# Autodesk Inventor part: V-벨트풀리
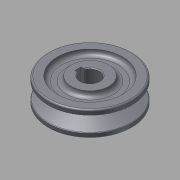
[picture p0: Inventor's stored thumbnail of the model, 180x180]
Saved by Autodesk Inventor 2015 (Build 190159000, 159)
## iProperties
Created: 2015-12
Part Number: V-벨트풀리
Material: 강철, 연강
Document SubType Name: Modeling
Designer: mdu
Density: 7.86 g/cm^3
Appearance: 강철
CustomPartVersion: 1
Author: mdu
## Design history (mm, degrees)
sketch "주 스케치"
  geometry: L1 (0, 16)-(27, 16); L2 (27, 16)-(27, 12.861); L3 (27, 12.861)-(16, 9.498); L4 (16, 9.498)-(16, 6.502); L5 (16, 6.502)-(27, 3.139); L6 (27, 3.139)-(27, 0); L7 (27, 0)-(0, 0); L8 (25, 12.25)-(25, 3.75); L9 (16, 8)-(25, 8); L10 (27, 12.861)-(27, 3.139); L11 (0, -3)-(0, 18) reference; L12 (0, 0)-(0, 16)
  constraints: 22 end point, 5 perpendicular, 2 collinear, 2 midpoint, 2 point on line, 1 parallel
  dimensions: "d0" = 8.5 distance of L8.start L8.end (= da_Bw); "d1" = 34 deg angle of L3 L5 (= da_Alfa); "d2" = 2 distance between parallel lines of L2 L8 (= da_c); "d6" = 16 distance between parallel lines of L7 L1 (computed from d5, da_ng, da_Sg); "d21" = 50 diameter of L8 L11 (= da_Dw); "d25" = 11 distance between parallel lines of L4 L10 (= da_Hd); "d27" = 8 distance between parallel lines of L7 L9 (= da_Se)
node "벨트 평면"
revolve "본체" stored, may be unused: angle "d7" = 90 deg
revolve "그루브" stored, may be unused: angle "d15" = 90 deg
feature "허브 키홈"
fillet "모깎기3" dims "d28" = 0.5, "d29" = 1, "d30" = 1
sketch "스케치2"
  geometry: C1 r 12 at (0, 0); C2 r 21 at (0, 0); 1 further point
  constraints: 2 centre point, 2 coincident
  dimensions: "d31" = 24 diameter of C1; "d32" = 42 diameter of C2
extrude "돌출1" cut sketch "스케치2" distance "d33" = 3; taper "d34" = 0 deg
fillet "모깎기4" dims "d35" = 3
node "작업 평면2"
chamfer "모따기1" distance "d36" = 0.5; stored, may be unused: second distance "d37" = 2, angle "d38" = 45 deg
body "Solid1"
pattern_linear "그루브 패턴" dims "d18" = 12 (= da_Sg)
mirror "대칭1"
other parameters: "d5" = 8 (= da_Se), "da_Bw" = 8.5 [user parameter; used in 1 equation term], "da_Alfa" = 34 deg [user parameter; used in 1 equation term], "da_c" = 2 [user parameter; used in 1 equation term], "da_Dw" = 50 [user parameter; used in 1 equation term], "da_Hd" = 11 [user parameter; used in 1 equation term], "da_Se" = 8 [user parameter; used in 2 equation terms], "da_Sg" = 12 [user parameter; used in 2 equation terms], "da_r1" = 0 [user parameter], "da_r2" = 0 [user parameter], "d24" = 0, "d26" = 0
